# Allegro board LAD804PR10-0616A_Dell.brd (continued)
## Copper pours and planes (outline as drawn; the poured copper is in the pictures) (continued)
LX1_APU on BOTTOM (solid shape): 153.44,71.33 156.04,71.33 156.23,71.14 156.23,68.15 156.1,68.03 154.64,68.03 154.26,67.65 154.26,65.17 154.01,64.92 146.71,64.92 145.94,65.68 145.94,69.68 146.83,69.68 146.83,70.57 145.94,70.57 145.94,71.96 146.13,72.15 152.61,72.15
LX1_APU on IN2 (solid shape): 154.58,70.88 154.58,69.8 154.52,69.74 153.56,69.74 153.44,69.87 153.44,70.82 153.56,70.95 154.52,70.95
LX1_APU on IN2 (solid shape): 161.37,62.95 161.37,61.23 161.32,61.23 161.26,61.17 160.8,61.17 160.61,61.36 160.61,62.95 160.74,63.07 161.25,63.07
LX1_VGA on TOP (solid shape): 57.3,122.32 57.61,122.01 58.63,122.01 58.76,121.88 58.76,121.37 58.63,121.25 57.65,121.25 57.59,121.27 56.85,122.01 56.74,122.01 56.69,122.04 56.6,122.13 55.71,122.13 55.64,122.2 55.64,122.26 55.71,122.32 56.73,122.32
LX1_VGA on TOP (solid shape): 76.22,120.16 76.22,118.65 76.19,118.64 75.99,118.36 76.12,118.05 76.15,117.97 76.12,117.89 75.99,117.64 76.09,117.37 76.12,117.3 75.99,116.99 76.12,116.67 76.09,116.6 76,116.29 76.19,116.03 76.22,116.02 76.22,113.43 75.97,113.18 72.41,113.18 72.22,113.37 72.22,114.95 71.78,115.4 69.62,115.4 69.3,115.72 69.3,120.29 69.49,120.48 75.9,120.48
LX1_VGA on BOTTOM (solid shape): 75.84,120.16 75.84,115.4 75.97,115.27 77.68,115.27 78.06,114.89 78.06,111.02 78.95,111.02 78.95,112.1 79.01,112.16 80.35,112.16 80.54,111.97 80.54,109.75 80.28,109.49 75.65,109.49 75.39,109.75 75.39,110.89 75.2,111.08 72.98,111.08 72.66,111.4 72.66,115.4 72.47,115.59 69.55,115.59 69.3,115.84 69.3,120.29 69.49,120.48 75.52,120.48
LX1_VGA on IN2 (solid shape): 57.87,121.69 58.57,121.69 58.57,121.68 58.82,121.43 58.82,120.92 58.76,120.86 58.06,120.86 56.98,121.94 56.98,122.07 57.17,122.26 57.3,122.26
LX1_VGA on IN2 (solid shape): 74.67,118.85 74.7,118.79 74.7,118.48 74.69,118.47 74.66,118.32 74.69,118.17 74.7,118.16 74.7,117.85 74.67,117.79 74.63,117.75 74.12,117.75 73.93,117.56 73.55,117.56 73.49,117.62 73.49,118.83 73.55,118.89 74.63,118.89
LX2_VGA on TOP (solid shape): 59.07,124.8 59.07,124.29 59.01,124.23 57.3,124.23 57.17,124.1 55.77,124.1 55.71,124.17 55.71,124.29 55.77,124.36 56.79,124.36 56.85,124.42 57.17,124.42 57.49,124.74 57.8,124.74 57.93,124.86 59.01,124.86
LX2_VGA on TOP (solid shape): outline of 87 points within 69.3,121.43 77.43,131.97
LX2_VGA on BOTTOM (solid shape): 78.08,131.88 78.08,130.21 77.06,130.21 77.06,129.41 78.02,129.41 78.02,128.06 77.97,128.01 77.53,128.01 77.49,127.97 77.49,124.1 77.3,123.91 74.7,123.91 74.32,123.53 74.32,121.81 74.19,121.68 69.36,121.68 69.24,121.81 69.24,125.88 69.55,126.19 73.87,126.19 73.87,126.19 74.43,126.19 74.72,126.49 74.72,127.99 74.17,128.54 73.4,128.54 73.11,128.83 73.11,131.77 73.31,131.97 77.98,131.97
LX2_VGA on IN2 (solid shape): 59.58,125.5 59.58,125.44 58.44,124.29 57.42,124.29 57.36,124.36 57.36,124.61 58.57,125.82 59.26,125.82
LX2_VGA on IN2 (solid shape): 77.48,128.05 77.48,124.25 77.32,124.1 75.23,124.1 74.66,124.67 74.66,127.72 75.08,128.14 77.38,128.14
LX_1.2V on TOP (solid shape): 78.38,104.67 78.38,103.33 78.32,103.27 77.52,103.27 77.46,103.33 77.46,103.9 77.05,104.32 77.05,105.3 77.17,105.43 77.62,105.43
LX_1.2V on BOTTOM (solid shape): 77.68,106.76 77.68,103.59 78.19,103.08 81.05,103.08 81.11,103.02 81.11,102.06 80.98,101.94 74.63,101.94 74.19,102.38 74.19,106.83 74.32,106.95 77.49,106.95
LX_1.2V on BOTTOM (solid shape): 85.36,106.13 85.49,106.13 86.51,105.11 86.51,104.35 86.44,104.29 86.32,104.29 86.25,104.35 86.25,104.79 85.94,105.11 85.81,105.11 85.36,105.56 84.54,105.56 84.41,105.68 84.41,106.32 84.48,106.38 85.11,106.38
LX_1.2V on IN2 (solid shape): 77.87,105.3 77.87,103.21 77.74,103.08 77.11,103.08 76.98,103.21 76.98,105.3 77.11,105.43 77.74,105.43
LX_1.2V on IN2 (solid shape): 86.19,105.43 86.19,105.24 86.06,105.11 85.81,105.11 85.65,105.27 84.76,105.27 84.41,105.62 84.41,106 84.48,106.06 85.55,106.06
LX_1.8VALW on TOP (solid shape): 37.68,101.62 37.68,99.97 37.61,99.9 36.58,99.9 36.5,99.95 36.49,100.04 36.4,100.41 36.03,100.49 35.94,100.51 35.9,100.59 35.9,101.49 36.09,101.68 37.61,101.68
LX_1.8VALW on BOTTOM (solid shape): 38.66,103.99 38.66,103.37 38.76,103.27 39.52,103.27 39.71,103.08 39.71,99.84 36.56,99.84 36.47,99.89 36.47,99.99 36.42,100.39 36.03,100.49 35.94,100.51 35.9,100.59 35.9,101.63 35.94,101.71 36.03,101.73 36.37,101.78 36.51,102.08 36.53,102.16 36.61,102.19 37.68,102.19 37.8,102.32 37.8,103.97 37.9,104.07 38.58,104.07
LX_3V on TOP (solid shape): 172.36,49.68 172.36,49.17 172.49,49.04 172.93,49.04 172.99,48.98 172.99,48.15 172.8,47.96 172.3,47.96 171.22,49.04 169.88,49.04 169.69,49.23 169.69,50.18 169.88,50.37 171.66,50.37
LX_3V on BOTTOM (solid shape): 177.69,48.79 177.69,48.21 177.44,47.96 176.61,47.96 176.55,48.02 176.55,48.35 176.56,48.4 176.56,48.43 176.56,48.86 176.68,48.98 177.5,48.98
LX_3V on BOTTOM (solid shape): 172.61,50.23 172.61,49.76 172.58,49.74 172.54,49.13 173.09,49.39 173.13,49.46 173.2,49.48 173.69,49.48 174.25,48.92 174.25,48.43 174.26,48.4 174.26,48.36 174.26,47.58 174.2,47.52 173.45,47.52 173.45,47.52 173.03,47.52 173.02,47.55 172.55,47.79 172.35,47.3 172.37,47.27 172.3,47.2 172.3,45.23 172.17,45.1 171.63,45.1 171.54,45.19 171.34,45.19 171.21,45.17 171.1,45.1 169.76,45.1 169.63,45.23 169.63,49.9 170.03,50.31 172.54,50.31
LX_3V on IN2 (solid shape): 177.69,48.85 177.69,48.21 177.44,47.96 172.55,47.96 172.36,48.15 172.36,48.91 172.49,49.04 177.5,49.04
LX_5V on TOP (solid shape): 189.55,42.69 189.55,41.7 189.4,41.55 187.7,41.55 187.69,41.55 187.56,41.58 187.43,41.57 187.4,41.56 187.28,41.67 187.28,42.75 187.41,42.88 189.36,42.88
LX_5V on BOTTOM (solid shape): 199.6,38.88 199.6,38.05 199.41,37.86 198.14,37.86 198.08,37.93 198.08,38.12 198.33,38.37 198.33,38.69 198.65,39.01 199.47,39.01
LX_5V on BOTTOM (solid shape): outline of 169 points within 187.15,37.48 195.85,42.75
LX_5V on IN2 (solid shape): 196.24,38.94 199.54,38.94 199.6,38.88 199.6,37.99 199.47,37.86 196.11,37.86 195.66,37.42 194.46,37.42 194.2,37.67 194.2,38.84 194.74,38.84 194.74,38.79 194.74,38.74 194.76,38.69 194.78,38.64 194.81,38.59 194.85,38.56 194.89,38.52 194.94,38.5 194.99,38.48 195.04,38.46 195.09,38.46 195.15,38.46 195.2,38.48 195.25,38.5 195.29,38.52 195.33,38.56 195.37,38.59 195.4,38.64 195.42,38.69 195.44,38.74 195.45,38.79 195.45,38.84 195.44,38.9 195.42,38.95 195.4,38.99 195.37,39.04 195.33,39.08 195.29,39.11 195.25,39.14 195.2,39.16 195.15,39.17 195.09,39.17 195.04,39.17 194.99,39.16 194.94,39.14 194.89,39.11 194.85,39.08 194.81,39.04 194.78,38.99 194.76,38.95 194.74,38.9 194.74,38.84 194.2,38.84 194.2,39.13 194.46,39.39 195.79,39.39
LX_+1.35VGPU on BOTTOM (solid shape): 158.64,89.55 158.64,89.17 158.2,88.73 157.37,88.73 157.31,88.79 157.31,89.12 157.31,89.12 157.31,89.55 157.44,89.68 158.52,89.68
LX_+1.35VGPU on BOTTOM (solid shape): 152.55,92.98 152.55,92.09 152.8,91.84 154.07,91.84 154.13,91.78 154.13,90.32 154.9,89.55 154.9,89.05 155.02,88.92 155.02,88.41 154.9,88.28 153.12,88.28 152.99,88.16 152.99,86.95 152.55,86.51 150.71,86.51 150.52,86.7 150.52,92.92 150.71,93.11 152.42,93.11
LX_+1.35VGPU on IN2 (solid shape): 158.58,89.62 158.58,89.11 158.2,88.73 153.56,88.73 153.37,88.92 153.37,89.55 153.56,89.74 158.45,89.74
LX_NB on TOP (solid shape): 165.63,58.37 165.63,57.23 165.88,56.98 165.88,55.9 165.76,55.77 165.76,55.45 165.56,55.26 164.87,55.26 164.74,55.39 164.74,55.83 164.8,55.9 165.11,55.9 165.25,55.9 165.37,56.03 165.37,58.37 165.44,58.44 165.56,58.44
LX_NB on TOP (solid shape): 155.15,53.87 158.64,53.87 158.96,53.55 158.96,47.64 158.83,47.52 154.13,47.52 153.94,47.71 153.94,48.41 153.82,48.53 153.66,48.53 153.61,48.54 153.44,48.72 153.44,48.98 153.06,49.36 151.34,49.36 151.21,49.48 151.21,54.88 151.4,55.07 153.94,55.07
LX_NB on BOTTOM (solid shape): outline of 133 points within 150.13,47.45 158.83,56.53
LX_NB on IN2 (solid shape): 155.25,54.85 155.25,53.93 155.18,53.87 153.4,53.87 153.28,53.99 153.28,54.91 153.37,55.01 155.09,55.01
LX_NB on IN2 (solid shape): 165.88,57.04 165.88,55.41 165.88,55.39 165.88,55.14 165.69,54.95 165.25,54.95 165.12,55.07 165.12,55.64 165.37,55.9 165.37,57.04 165.44,57.1 165.82,57.1
LX_VDDP_ALWP on TOP (solid shape): 160.1,36.4 160.1,34.94 159.6,34.44 159.6,33.29 159.53,33.23 159.41,33.23 159.34,33.29 159.34,36.4 159.41,36.47 160.04,36.47
LX_VDDP_ALWP on TOP (solid shape): 151.34,40.53 151.34,37.61 151.15,37.42 149.88,37.42 149.56,37.1 149.56,35.83 148.67,34.94 148.67,30.88 148.55,30.75 145.37,30.75 145.12,30.5 144.52,30.5 144.14,30.88 144.14,38.42 146.44,40.72 151.15,40.72
LX_VDDP_ALWP on BOTTOM (solid shape): 150.89,40.15 150.89,38.91 153.5,36.3 153.5,34.63 153.25,34.37 151.48,34.37 151.47,34.4 151.43,34.46 151.38,34.52 151.34,34.59 151.38,34.67 151.5,35.02 151.25,35.28 151.18,35.36 151.21,35.45 151.21,35.95 150.71,35.96 150.64,35.93 150.57,35.96 149.97,35.71 150.57,35.45 150.64,35.48 150.71,35.45 150.78,35.4 150.86,35.36 150.93,35.29 150.9,35.2 150.79,34.93 150.92,34.67 150.96,34.59 150.92,34.52 150.87,34.46 150.83,34.4 150.82,34.37 150.13,34.37 149.05,35.45 146.07,35.45 145.69,35.83 145.69,40.4 145.89,40.61 150.43,40.61
LX_VDDP_ALWP on IN2 (solid shape): 150.01,37.74 150.01,36.47 149.94,36.4 149.18,36.4 148.99,36.59 148.99,37.61 149.18,37.8 149.94,37.8
LX_VDDP_ALWP on IN2 (solid shape): 160.23,36.21 160.23,34.75 160.04,34.56 159.53,34.56 159.41,34.69 159.41,35.45 158.83,36.02 158.83,36.09 159.21,36.47 159.98,36.47
MCT0 on TOP (solid shape): 19.26,112.54 19.26,111.52 19.2,111.46 17.61,111.46 17.55,111.52 17.55,112.67 17.61,112.73 19.07,112.73
MCT0 on BOTTOM (solid shape): 17.99,112.54 19.83,112.54 20.09,112.29 20.09,111.52 20.02,111.46 17.55,111.46 17.52,111.51 17.48,111.56 17.48,112.48 17.61,112.6 17.93,112.6
MCT1 on TOP (solid shape): 19.26,109.05 19.26,108.03 19.13,107.9 17.67,107.9 17.61,107.97 17.61,109.05 17.67,109.11 19.2,109.11
MCT1 on BOTTOM (solid shape): 18.5,108.79 19.96,108.79 20.21,108.54 20.21,108.03 20.09,107.9 17.74,107.9 17.55,108.1 17.55,108.92 17.74,109.11 18.18,109.11
Net_18 on TOP (solid shape): 152.04,83.37 144.04,83.37 144.04,91.37 152.04,91.37
Net_19 on TOP (solid shape): 208.13,15.89 200.13,15.89 200.13,23.89 208.13,23.89
PHASE_CHG on TOP (solid shape): 210.33,32.02 210.33,30.82 210.52,30.63 211.48,30.63 211.79,30.31 211.79,27.39 211.67,27.26 209.38,27.26 209,27.64 207.47,27.64 207.41,27.7 207.41,31.7 207.79,32.09 210.27,32.09
PHASE_CHG on TOP (solid shape): 209.75,42.11 209.9,42.08 210.05,42.11 210.06,42.12 210.14,42.12 210.23,42.03 210.42,42.03 210.46,41.99 211.91,41.99 211.91,41.8 211.84,41.74 210.4,41.74 210.24,41.58 209.22,41.58 209,41.36 209,40.79 208.87,40.66 208.33,40.66 208.25,40.73 208.25,41.32 208.34,41.32 208.91,41.88 208.91,41.94 209.05,42.08 209.12,42.08 209.14,42.07 209.42,42.07 209.43,42.08 209.44,42.08 209.48,42.12 209.74,42.12
PHASE_CHG on BOTTOM (solid shape): outline of 121 points within 207.03,27.58 214.08,32.85
PHASE_CHG on IN2 (solid shape): 209.32,29.86 209.32,28.97 209.19,28.85 208.24,28.85 208.11,28.97 208.11,29.99 208.24,30.12 209.06,30.12
PHASE_CHG on IN2 (solid shape): 209.75,42.11 209.9,42.08 210.05,42.11 210.06,42.12 210.33,42.12 210.4,42.06 210.4,41.17 210.14,40.91 209.25,40.91 209.06,41.1 209.06,41.93 209.21,42.07 209.23,42.07 209.35,42.07 209.46,42.12 209.74,42.12
RING2 on TOP (solid shape): 24.34,27.84 24.91,27.84 24.97,27.85 25.03,27.86 25.06,27.87 25.1,27.83 25.1,27.77 25.04,27.7 23,27.7 22.94,27.76 22.94,28.24 23.04,28.34 23.84,28.34
RING2 on BOTTOM (solid shape): 22.94,15.58 22.94,14.81 22.82,14.69 21.23,14.69 21.17,14.75 21.17,15.51 21.61,15.96 22.56,15.96
RING2 on IN2 (solid shape): 22.75,16.78 22.75,15.64 22.56,15.45 21.77,15.45 21.42,15.8 21.42,16.72 21.67,16.97 22.56,16.97
RING2 on IN2 (solid shape): 24.02,28.47 24.02,27.89 23.9,27.77 22.44,27.77 22.37,27.7 21.61,27.7 21.55,27.77 21.55,28.47 21.67,28.59 23.9,28.59
RING2_R on BOTTOM (solid shape): 17.48,13.77 17.48,13.04 17.23,12.78 15.7,12.78 15.26,13.23 15.26,14.24 15.39,14.37 16.89,14.37
RING2_R on BOTTOM (solid shape): 20.91,14.69 20.91,14.64 21.12,14.43 22.05,14.43 22.05,13.99 21.93,13.86 19.96,13.86 19.58,14.24 19.58,15.32 19.64,15.39 20.21,15.39
RING2_R on BOTTOM (solid shape): 4.72,13.8 4.72,12.21 4.53,12.02 3.13,12.02 3.07,12.08 3.07,12.09 2.78,12.38 2.78,13.75 3.02,13.99 4.53,13.99
RING2_R on IN1 (solid shape): 20.28,15.32 20.28,14.37 20.02,14.12 16.85,14.12 15.9,13.16 15.39,13.16 15.07,13.48 15.07,14.31 16.21,15.45 20.15,15.45
SLEEVE on TOP (solid shape): 24.4,27.51 25.31,27.51 25.37,27.45 25.37,27.31 25.32,27.26 24.34,27.26 24.21,27.13 23.96,27.13 23.93,27.11 23.93,27.11 23.7,26.88 23.13,26.88 22.95,27.06 22.95,27.46 23.07,27.58 24.34,27.58
SLEEVE on BOTTOM (solid shape): 23.01,18.62 23.01,17.5 22.92,17.42 21.23,17.42 21.17,17.48 21.17,18.56 21.36,18.75 22.88,18.75
SLEEVE on IN2 (solid shape): 23.01,19.7 23.01,18.24 22.82,18.05 21.86,18.05 21.74,18.18 21.74,19.77 21.8,19.83 22.88,19.83
SLEEVE on IN2 (solid shape): 24.66,27.32 24.66,26.5 24.59,26.43 23.07,26.43 22.85,26.66 22.85,27.29 23.07,27.51 24,27.51 24.07,27.58 24.4,27.58
SLEEVE_R on BOTTOM (solid shape): 21.1,17.16 21.12,17.16 21.99,17.16 22.05,17.1 22.05,16.4 21.99,16.34 20.78,16.34 20.53,16.08 19.32,16.08 19.2,16.21 19.2,17.1 19.32,17.23 21.04,17.23
SLEEVE_R on BOTTOM (solid shape): 4.15,25.1 4.15,22.88 3.89,22.62 2.18,22.62 1.99,22.81 1.99,24.74 2.48,24.96 2.9,25.29 3.96,25.29
SNUB_+1.35VGPU on BOTTOM (solid shape): 149.82,92.98 149.82,91.27 149.75,91.2 147.66,91.2 147.59,91.27 147.59,92.28 147.66,92.35 148.42,92.35 148.48,92.41 148.48,92.98 148.55,93.05 149.75,93.05
SPK_L+_CONN on TOP (solid shape): 43.77,6.3 43.77,5.03 42.76,5.03 42.69,5.1 42.69,6.18 42.88,6.37 43.71,6.37
SPK_L+_CONN on TOP (solid shape): 38.37,27.7 38.37,27.07 38.18,26.88 36.52,26.88 36.3,27.1 36.3,27.74 36.45,27.89 38.18,27.89
SPK_L+_CONN on TOP (solid shape): 10.82,11 10.82,9.86 10.75,9.8 10.31,9.8 10.24,9.86 10.24,10.24 10.12,10.37 9.48,10.37 9.42,10.43 9.42,10.94 9.55,11.07 10.75,11.07
SPK_L+_CONN on BOTTOM (solid shape): 10.75,11 10.75,9.86 10.12,9.23 10.12,4.91 10.05,4.84 9.61,4.84 9.48,4.97 9.48,6.88 9.29,7.07 9.29,8.1 9.29,8.12 9.29,8.63 9.29,8.65 9.29,9.67 9.1,9.86 9.1,10.94 9.35,11.19 10.56,11.19
SPK_L+_CONN on IN2 (solid shape): 43.84,5.73 43.84,4.91 43.77,4.84 42.12,4.84 41.99,4.97 41.99,5.8 42.06,5.86 43.71,5.86
SPK_L+_CONN on IN2 (solid shape): 11.07,10.94 11.07,9.16 11.2,9.04 11.2,8.46 10.5,8.46 10.12,8.84 10.12,11 10.18,11.07 10.94,11.07
SPK_L-_CONN on TOP (solid shape): 45.36,4.91 45.36,3.83 45.23,3.7 44.15,3.7 44.03,3.83 44.03,4.78 44.22,4.97 45.3,4.97
SPK_L-_CONN on TOP (solid shape): 38.44,29.04 38.44,28.28 38.37,28.21 36.45,28.21 36.3,28.36 36.3,29 36.46,29.16 38.31,29.16
SPK_L-_CONN on TOP (solid shape): 8.97,11 8.97,9.99 8.85,9.86 8.4,9.86 8.11,10.15 8.11,10.17 8.1,10.17 8.08,10.18 7.39,10.18 7.32,10.24 7.32,10.94 7.45,11.07 8.91,11.07
SPK_L-_CONN on BOTTOM (solid shape): 8.85,11.07 8.85,9.99 7.89,9.04 7.89,7.38 8.59,6.69 8.91,6.69 9.16,6.43 9.16,4.97 9.04,4.84 8.53,4.84 8.4,4.97 8.4,5.67 7.07,7 7.07,11 7.26,11.19 8.72,11.19
SPK_L-_CONN on IN2 (solid shape): 9.1,11 9.1,9.23 9.04,9.16 8.28,9.16 8.15,9.29 8.15,11.07 8.21,11.13 8.97,11.13
SPK_L-_CONN on IN2 (solid shape): 45.42,4.34 45.42,3.57 45.3,3.45 43.58,3.45 43.33,3.7 43.33,4.34 43.45,4.46 45.3,4.46
SPK_R+_CONN on TOP (solid shape): 14.88,11.07 14.88,10.11 14.75,9.99 14.43,9.99 14.12,10.31 13.42,10.31 13.36,10.37 13.36,11.07 13.42,11.13 14.82,11.13
SPK_R+_CONN on TOP (solid shape): 47.96,8.46 47.96,7.51 47.84,7.38 46.76,7.38 46.69,7.45 46.69,8.08 46.57,8.21 46.57,8.59 46.63,8.65 47.77,8.65
SPK_R+_CONN on TOP (solid shape): 38.5,31.64 38.5,30.82 38.44,30.75 37.99,30.75 37.84,30.74 37.69,30.69 36.49,30.69 36.29,30.89 36.29,31.55 36.52,31.77 38.37,31.77
SPK_R+_CONN on BOTTOM (solid shape): 14.88,11.13 14.88,10.11 14.31,9.54 14.31,7.96 12.21,5.86 12.21,4.97 12.15,4.91 11.64,4.91 11.51,5.03 11.51,6.39 11.54,6.4 11.6,6.44 11.66,6.48 12.56,7.38 12.78,7.38 12.92,7.52 12.93,7.52 13.17,7.67 13.32,7.91 13.32,7.93 13.42,8.02 13.42,9.48 13.16,9.73 13.16,11 13.36,11.19 14.82,11.19
SPK_R+_CONN on IN1 (solid shape): 15.9,11.04 15.9,10.08 15.77,9.96 14.56,9.96 14.37,10.15 14.37,11.04 14.5,11.16 15.77,11.16
SPK_R+_CONN on IN1 (solid shape): 47.96,8.15 47.96,7.51 47.71,7.26 46.12,7.26 46.06,7.32 46.06,8.21 46.12,8.27 47.84,8.27
SPK_R-_CONN on TOP (solid shape): 46.38,7.64 46.38,7.07 46.57,6.88 46.57,6.5 46.44,6.37 45.36,6.37 45.3,6.43 45.3,7.45 45.55,7.7 46.31,7.7
SPK_R-_CONN on TOP (solid shape): 12.91,11.07 12.91,9.86 12.85,9.8 12.47,9.8 12.34,9.92 12.34,10.11 12.21,10.24 11.39,10.24 11.32,10.31 11.32,11 11.45,11.13 12.85,11.13
SPK_R-_CONN on TOP (solid shape): 38.37,30.37 38.37,29.55 38.31,29.48 37.99,29.48 37.84,29.47 37.69,29.42 36.49,29.42 36.29,29.62 36.29,30.26 36.46,30.43 38.31,30.43
SPK_R-_CONN on BOTTOM (solid shape): 12.91,11.07 12.91,9.92 12.02,9.04 12.02,8.59 11.13,7.7 11.13,7.03 11.12,7.02 11.01,6.74 11.13,6.46 11.13,5.03 10.94,4.84 10.56,4.84 10.43,4.97 10.43,8.65 11.2,9.42 11.2,11 11.39,11.19 12.78,11.19
SPK_R-_CONN on IN1 (solid shape): 13.64,11.07 13.64,9.99 14.18,9.45 14.18,8.84 13.86,8.53 13.16,8.53 12.31,9.38 12.31,11.13 12.37,11.19 13.51,11.19
SPK_R-_CONN on IN1 (solid shape): 46.57,6.88 46.57,6.11 46.44,5.99 44.43,5.99 44.38,6.03 44.38,6.76 44.56,6.94 46.5,6.94
T-GND_L on TOP (solid shape): 22.12,119.08 22.12,117.43 21.23,116.54 21.23,108.16 21.04,107.97 19.96,107.97 19.9,108.03 19.9,119.02 20.15,119.27 21.93,119.27
T-GND_L on BOTTOM (solid shape): 23.45,119.27 23.45,117.56 23.26,117.37 21.29,117.37 21.1,117.56 21.1,119.27 21.23,119.4 23.32,119.4
TPAN_VDD_F on TOP (solid shape): 229.95,33.93 229.95,28.15 229.89,28.09 226.91,28.09 226.72,28.28 226.72,30.43 227.54,31.26 227.54,33.93 227.67,34.05 229.83,34.05
UG1_APU on TOP (solid shape): 163.15,61.93 163.35,61.93 164.49,61.93 164.55,61.87 164.55,61.74 164.49,61.68 163.02,61.68 162.96,61.61 162.01,61.61 161.95,61.68 161.95,62.06 162.01,62.12 162.96,62.12
UG1_APU on BOTTOM (solid shape): 156.23,72.66 156.23,72.03 156.17,71.96 153.82,71.96 153.75,72.03 153.75,72.66 153.82,72.73 156.17,72.73
UG1_APU on IN2 (solid shape): 155.98,72.41 155.98,71.84 155.86,71.73 154.88,71.73 154.86,71.71 153.88,71.71 153.72,71.87 153.72,72.44 153.88,72.6 155.79,72.6
UG1_APU on IN2 (solid shape): 162.98,63.12 163,63.02 162.93,62.95 162.66,62.57 162.99,62.25 163.06,62.22 163.09,62.15 163.09,61.8 162.96,61.68 162.01,61.68 161.95,61.74 161.95,63.07 162.01,63.14 162.96,63.14
UG1_VGA on TOP (solid shape): 56.67,121.88 56.79,121.88 57.68,120.99 57.68,120.74 57.61,120.67 57.3,120.67 56.79,121.18 56.79,121.33 56.79,121.34 56.81,121.44 56.79,121.53 56.79,121.56 56.66,121.69 55.77,121.69 55.71,121.75 55.71,121.88 55.77,121.94 56.61,121.94
UG1_VGA on BOTTOM (solid shape): 74.63,110.76 74.63,109.94 74.44,109.75 72.73,109.75 72.6,109.87 72.6,110.7 72.79,110.89 74.51,110.89
UG1_VGA on IN2 (solid shape): 74.73,111.49 74.73,109.97 74.54,109.78 73.52,109.78 73.39,109.9 73.39,111.56 73.55,111.71 74.51,111.71
UG1_VGA on IN2 (solid shape): 58.12,120.61 58.44,120.61 58.63,120.42 58.63,119.91 58.57,119.85 58.07,119.85 58.06,119.88 57.88,120.04 57.63,120.06 57.61,120.05 56.72,120.93 56.72,121.31 56.98,121.56 57.17,121.56
UG2_VGA on TOP (solid shape): 57.68,125.31 57.68,125.12 57.11,124.55 56.8,124.55 55.77,124.55 55.71,124.61 55.71,124.67 55.77,124.74 56.66,124.74 57.04,125.12 57.04,125.18 57.3,125.44 57.55,125.44
UG2_VGA on BOTTOM (solid shape): 74.56,127.93 74.56,126.76 74.37,126.57 73.27,126.57 73.1,126.75 73.1,127.94 73.29,128.14 74.35,128.14
UG2_VGA on IN2 (solid shape): 74.3,127.15 74.3,126.57 74.24,126.51 72.4,126.51 72.33,126.57 72.33,127.27 72.4,127.34 74.11,127.34
UG2_VGA on IN2 (solid shape): 58.88,126.52 58.88,126.39 57.23,124.74 57.23,124.67 57.11,124.55 56.91,124.55 56.79,124.67 56.79,125.63 57.8,126.64 58.76,126.64
UG_1.2V on BOTTOM (solid shape): 79.08,105.64 79.08,104.16 78.95,104.03 78.45,104.03 78.38,104.03 78.32,104.09 78.32,105.62 78.44,105.75 78.97,105.75
UG_1.2V on BOTTOM (solid shape): 86.89,105.75 86.89,104.3 86.84,104.25 86.73,104.25 86.67,104.31 86.67,105.14 86,105.81 86,106 86.19,106.19 86.44,106.19
UG_1.2V on IN2 (solid shape): 79.78,105.75 79.78,104.79 79.59,104.6 78.57,104.6 78.44,104.73 78.44,105.81 78.51,105.87 79.65,105.87
UG_1.2V on IN2 (solid shape): 86.95,106 86.95,105.43 86.76,105.24 86.63,105.24 85.43,106.44 85.43,106.51 85.68,106.76 86.19,106.76
UG_NB on TOP (solid shape): 165.25,58.37 165.24,58.32 165.24,57.51 165.25,57.48 165.25,56.22 165.06,56.03 164.8,56.03 164.74,56.09 164.74,57.1 164.93,57.3 164.93,57.37 164.93,58.37 164.99,58.44 165.18,58.44
UG_NB on BOTTOM (solid shape): 155.28,58.06 155.28,57.17 155.09,56.98 153.94,56.98 153.82,57.1 153.82,58.12 153.88,58.18 155.15,58.18
UG_NB on IN2 (solid shape): 155.91,58.12 155.91,57.3 155.85,57.23 153.88,57.23 153.82,57.3 153.82,58.12 153.88,58.18 155.85,58.18
UG_NB on IN2 (solid shape): 165.18,57.3 165.18,56.09 165.12,56.03 164.49,56.03 163.98,56.53 163.98,57.36 164.04,57.42 165.06,57.42
UG_VDDP_ALWP on TOP (solid shape): 151.28,36.72 151.28,35.51 151.15,35.39 150.07,35.39 149.94,35.51 149.94,36.72 150.01,36.78 151.21,36.78
UG_VDDP_ALWP on TOP (solid shape): 159.21,35.13 159.21,34.24 159.09,34.12 159.09,33.29 159.02,33.23 158.9,33.23 158.83,33.29 158.83,34.05 158.71,34.18 158.71,35.13 158.9,35.32 159.02,35.32
UG_VDDP_ALWP on IN2 (solid shape): 151.98,36.21 151.98,35.58 151.85,35.45 150.2,35.45 150.07,35.58 150.07,36.21 150.2,36.34 151.85,36.34
UG_VDDP_ALWP on IN2 (solid shape): 159.21,35.32 159.21,34.24 159.15,34.18 158.64,34.18 158.52,34.31 158.52,34.94 158.14,35.32 158.14,35.51 158.39,35.77 158.77,35.77
UGATE_CHG on TOP (solid shape): 211.94,41.52 211.94,41.36 211.87,41.28 211.84,41.3 211.8,41.31 211.75,41.32 211.05,41.32 211.03,41.31 210.9,41.24 210.83,41.1 210.82,41.09 210.77,41.06 210.72,41.03 210.47,40.78 209.38,40.78 209.31,40.85 209.31,41.44 209.32,41.45 210.02,41.45 210.09,41.44 210.16,41.45 210.29,41.45 210.32,41.48 210.33,41.48 210.46,41.61 211.86,41.61
VL on BOTTOM (solid shape): 196.17,35.96 196.17,35.26 195.79,34.88 195.79,33.87 195.79,33.8 195.72,33.73 195.7,33.74 195.57,33.73 195.45,33.67 194.84,33.67 194.77,33.74 194.77,34.56 195.92,35.71 195.92,35.96 195.98,36.02 196.11,36.02
N17382859 on BOTTOM (solid shape): 129.24,21.35 129.24,20.66 129.69,20.21 130.13,20.21 130.13,19.7 130.7,19.7 130.7,20.21 130.96,20.21 130.96,19.7 131.53,19.7 131.53,20.21 132.41,20.21 133.95,18.67 133.95,15.99 134.26,15.68 134.26,15 134.13,14.88 133.31,14.88 132.86,15.32 130.83,15.32 130,16.15 130,18.31 129.75,18.56 129.61,18.56 127.67,18.56 127.27,18.56 127.15,18.69 127.15,19.64 127.66,19.64 127.66,20.27 127.15,20.27 127.15,20.47 127.66,20.47 127.66,21.04 127.15,21.04 127.15,21.42 129.18,21.42
N17415515 on TOP (solid shape): 169.37,124.99 169.37,123.46 168.96,123.05 168.96,121.79 168.91,121.68 168.91,120.38 168.43,119.91 168.43,119.58 168.18,119.32 166.38,119.32 166.05,119.65 166.05,119.77 166.06,119.77 166.06,120.25 166.61,120.25 166.61,120.75 166.06,120.75 166.06,121.05 166.61,121.05 166.61,121.55 166.06,121.55 166.06,122.03 166.05,122.03 166.05,124.9 166.39,125.24 169.12,125.24
N17481633 on TOP (solid shape): 212.55,35.83 212.55,35.21 212.55,35.2 212.74,35.01 212.74,32.1 212.75,32.02 213.44,31.32 213.44,30.88 213.32,30.75 212.75,30.75 212.68,30.82 212.68,30.94 211.73,31.9 211.73,32.15 211.48,32.4 207.41,32.4 207.28,32.53 207.28,34.63 207.67,35.01 210.9,35.01 211.86,35.96 212.43,35.96
N17481633 on BOTTOM (solid shape): 208.36,38.5 210.65,38.5 211.22,37.93 211.47,37.93 211.47,37.93 212.43,37.93 212.49,37.86 212.49,36.21 212.68,36.02 212.68,33.17 213.44,32.4 213.44,31.7 213.38,31.64 211.98,31.64 211.03,32.59 211.03,33.1 210.9,33.23 207.47,33.23 207.35,33.36 207.35,36.02 207.86,36.02 207.86,36.85 207.35,36.85 207.35,37.23 207.86,37.23 207.86,38.05 207.35,38.05 207.35,38.69 207.47,38.82 208.05,38.82
N20135074 on TOP (solid shape): 70.89,114.95 70.89,113.24 70.82,113.18 69.74,113.18 69.36,113.56 68.73,113.56 68.66,113.62 68.66,114.51 68.73,114.57 69.36,114.57 69.81,115.02 70.82,115.02
N20135197 on TOP (solid shape): 71.2,128.92 71.2,127.21 71.14,127.15 69.93,127.15 69.87,127.21 69.87,127.46 69.81,127.53 69.04,127.53 68.98,127.59 68.98,128.86 69.11,128.99 71.14,128.99
N20135251 on TOP (solid shape): 53.61,127.59 53.61,125.31 53.55,125.25 52.66,125.25 52.6,125.31 52.6,127.65 52.74,127.79 53.41,127.79
N20141477 on TOP (solid shape): 153.06,49.04 153.06,47.33 152.74,47.01 151.47,47.01 151.21,47.26 151.21,49.04 151.28,49.1 152.99,49.1
N20141719 on TOP (solid shape): 148.99,66.5 148.99,65.42 148.61,65.04 148.61,64.34 148.55,64.28 147.66,64.28 147.59,64.34 147.59,65.11 147.15,65.55 147.15,66.57 147.21,66.63 148.86,66.63
N20277901 on BOTTOM (solid shape): 153.44,33.1 153.44,31.39 153.06,31.01 152.29,31.01 152.17,31.13 152.17,31.9 152.04,32.02 151.66,32.02 151.59,32.09 151.59,33.1 151.72,33.23 153.31,33.23
N21021316 on TOP (solid shape): 160.1,37.67 160.1,36.78 160.04,36.72 159.15,36.72 158.96,36.91 158.06,36.91 158.01,36.96 158.01,37.67 158.07,37.74 160.04,37.74
N21022260 on TOP (solid shape): 164.87,55.01 165.37,55.01 165.44,54.95 165.44,54.37 165.37,54.31 164.87,54.31 164.55,54.63 163.53,54.63 163.47,54.69 163.47,55.33 163.53,55.39 164.49,55.39
N21022300 on TOP (solid shape): 162.58,64.28 162.58,63.65 162.52,63.58 161.56,63.58 161.12,63.14 160.55,63.14 160.48,63.2 160.48,63.71 160.55,63.77 161.06,63.77 161.63,64.34 162.52,64.34
N22643429 on BOTTOM (solid shape): 36.09,116.86 36.79,116.86 37.23,116.41 37.23,115.91 37.17,115.84 36.66,115.84 35.71,116.79 35.07,116.79 35.01,116.86 35.01,116.92 35.07,116.99 35.96,116.99
N22657839 on TOP (solid shape): 26.31,32.91 26.31,32.34 27.01,31.64 27.01,30.71 27.07,30.65 27.07,29.84 27.02,29.79 26.91,29.79 26.85,29.85 26.85,30.75 26.88,30.78 26.88,31.07 26.85,31.1 26.86,31.12 26.75,31.38 26.48,31.49 26.46,31.49 26.12,31.83 25.75,31.83 25.37,32.21 23.96,32.21 23.83,32.34 23.83,32.9 23.86,32.93 24.44,32.93 24.49,32.97 26.25,32.97
N22661096 on TOP (solid shape): 26.69,24.54 26.69,23.39 26.06,22.75 26.05,22.74 26.05,21.35 25.93,21.23 24.34,21.23 24.21,21.35 24.21,22.12 24.82,22.72 25.64,22.72 26.44,23.51 26.44,24.52 26.51,24.59 26.63,24.59
N22662054 on TOP (solid shape): 28.47,32.66 28.47,32.32 28.21,32.07 28.19,32.07 27.82,31.81 27.9,31.35 27.9,29.85 27.84,29.79 27.7,29.79 27.64,29.85 27.64,30.88 27.51,31.01 27.51,32.36 27.46,32.41 27.46,32.63 27.57,32.73 28.39,32.73
N22663765 on TOP (solid shape): 27.07,24.53 27.07,23.2 27.01,23.13 27,22.91 27.01,22.86 27.01,22.43 27.11,22.33 27.11,21.23 26.31,21.23 26.18,21.35 26.18,22.69 26.82,23.32 26.82,24.55 26.87,24.6 27,24.6
N24135897 on TOP (solid shape): 123.85,8.08 123.85,7.45 124.33,6.96 124.34,6.95 124.72,6.56 125.27,6.61 125.28,6.62 125.31,6.62 125.81,7.13 130.26,7.13 131.08,6.3 132.04,6.3 132.42,5.92 132.42,5.39 132.15,5.12 130.74,5.12 129.43,6.43 126.19,6.43 125.99,6.23 123.1,6.23 122.38,6.94 122.38,7.96 122.7,8.27 123.65,8.27
N24135899 on TOP (solid shape): 119.46,11.07 119.46,8.34 119.22,8.09 119.22,6.9 119.88,6.24 120.99,6.24 121.56,5.67 121.56,4.78 121.31,4.53 120.67,4.53 120.54,4.65 120.54,4.84 119.5,5.89 119.39,6.03 119.26,6.13 119.25,6.14 118.7,6.69 118.7,9.1 117.88,9.92 117.88,10.94 118.19,11.26 119.27,11.26
N25997876 on BOTTOM (solid shape): 165.15,119.21 165.15,117.77 164.83,117.45 161.84,117.45 161.25,116.86 161.25,114.37 161.01,114.13 159.7,114.13 159.52,114.31 159.52,117.59 159.58,117.8 159.52,118 159.52,118.15 160.78,119.41 164.94,119.41
N25997876 on IN2 (solid shape): 165.15,119.21 165.15,117.77 164.83,117.45 161.84,117.45 161.25,116.86 161.25,114.37 161.01,114.13 159.72,114.13 159.6,114.25 159.6,118.24 160.78,119.41 164.94,119.41
N27700813 on BOTTOM (solid shape): outline of 97 points within 22.32,91.97 28.21,96.27
N27700813 on IN1: 13.71,87.37 14.31,87.37 14.64,87.04 14.64,86 14.63,85.98 14.63,82.11 15.16,81.58 15.16,79.15 14.92,78.91 14.22,78.91 14.04,79.09 14.04,81.21 13.47,81.78 13.47,87.13
N28714524 on TOP (solid shape): 212.94,40.72 212.94,37.55 212.81,37.42 211.73,37.42 211.67,37.48 211.67,38.3 211.69,38.33 211.74,38.38 212.33,38.38 212.38,38.44 212.62,38.44 212.75,38.56 212.75,40.72 212.81,40.79 212.87,40.79
N28714564 on TOP (solid shape): 207.92,39.55 207.73,39.36 206.97,39.36 206.9,39.42 206.9,40.37 207.28,40.75 207.28,41.32 207.92,41.32
N28714601 on TOP (solid shape): 213.38,40.66 213.38,39.55 213.38,39.54 213.34,39.39 213.38,39.24 213.38,39.22 213.37,39.12 213.38,39.02 213.38,39.01 213.39,39 213.47,38.87 213.6,38.79 213.82,38.56 213.82,37.55 213.76,37.48 213.13,37.48 213.06,37.55 213.06,39.77 213.13,39.83 213.13,40.66 213.19,40.72 213.32,40.72
N28714606 on TOP (solid shape): 211.48,31.96 211.48,31.01 211.41,30.94 210.59,30.94 210.52,31.01 210.52,31.96 210.59,32.02 211.41,32.02
N28714606 on TOP (solid shape): 210.35,39.97 210.35,39.16 210.04,38.85 209.77,38.85 209.67,38.75 208.87,38.75 208.81,38.82 208.81,39.2 208.87,39.26 209.19,39.26 209.32,39.39 209.32,40.05 209.37,40.1 210.22,40.1
N28714606 on IN2 (solid shape): 211.54,31.96 211.54,31.01 211.48,30.94 210.46,30.94 210.33,31.07 210.33,31.83 210.65,32.15 211.35,32.15
N28714606 on IN2 (solid shape): 210.08,39.13 210.08,38.73 210.21,38.61 210.21,38.18 210.08,38.05 209,38.05 208.81,38.25 208.81,39.13 209,39.32 209.89,39.32
N28714617 on BOTTOM (solid shape): 166.14,114.05 166.24,113.95 166.24,113.41 166.28,113.37 166.28,112.67 165.96,112.35 164.31,112.35 163.42,111.46 163.42,111.15 161.88,111.15 161.88,110.51 163.42,110.51 163.42,109.8 163.41,109.79 163.41,109.66 163.29,109.54 161.92,109.54 161.81,109.66 161.5,109.66 161.04,110.12 161.04,112.57 161.5,113.02 161.5,116.78 162.03,117.32 166.14,117.32
N28714693 on TOP (solid shape): 206.14,30.75 206.14,27.2 206.01,27.07 203.62,27.07 203.6,27.1 203.28,27.3 202.96,27.1 202.95,27.07 202.59,27.07 202.39,27.26 202.39,30.69 202.59,30.88 206.01,30.88
N28714693 on BOTTOM (solid shape): outline of 82 points within 203.47,24.28 216.11,29.04
N28714782 on BOTTOM (solid shape): 217,32.59 217,29.36 216.87,29.23 215.6,29.23 215.54,29.29 215.54,31.01 216.05,31.51 216.05,32.53 216.24,32.72 216.87,32.72
N28714793 on TOP (solid shape): 207.03,30.75 207.03,28.28 207.28,28.02 207.28,27.65 207.28,27.65 207.28,27.32 207.22,27.26 206.33,27.26 206.27,27.32 206.27,30.82 206.33,30.88 206.9,30.88
N33124395 on BOTTOM (solid shape): 84.48,102.89 85.99,102.89 86.07,102.81 86.07,102.68 86.03,102.63 84.42,102.63 84.28,102.63 84.16,102.51 84.16,102.37 84.16,101.17 84.09,101.11 83.46,101.11 83.4,101.17 83.4,101.34 83.4,101.35 83.46,101.56 83.4,101.77 83.4,102.11 83.46,102.32 83.4,102.53 83.4,103.21 83.46,103.27 84.09,103.27
N33124472 on TOP (solid shape): 77.3,103.87 77.3,103.33 76.86,102.89 76.86,101.3 76.73,101.17 75.84,101.17 75.78,101.24 75.78,103.71 76,103.94 77.24,103.94
N39282118 on BOTTOM (solid shape): 39.33,108.6 39.9,108.6 39.9,109.11 40.98,109.11 41.04,109.05 41.04,106.32 40.91,106.19 37.93,106.19 37.87,106.25 37.87,108.98 37.99,109.11 38.5,109.11 38.5,108.6 39.07,108.6 39.07,109.17 39.33,109.17
N39282176 on TOP (solid shape): 40.91,102.51 40.91,99.97 40.85,99.9 39.2,99.9 39.14,99.97 39.14,102.38 39.33,102.57 40.85,102.57
N39352229 on BOTTOM (solid shape): 172.74,51.01 173.51,51.01 173.6,50.92 173.6,49.95 173.55,49.9 172.82,49.9 172.77,49.95 172.77,50.46 172.64,50.59 171.95,50.59 171.9,50.64 171.9,51.15 171.98,51.23 172.52,51.23
N39352417 on BOTTOM (solid shape): 195.92,36.72 195.92,36.21 194.52,34.82 194.52,33.74 194.46,33.67 194.29,33.67 194.28,33.68 194.07,33.74 193.86,33.67 193.57,33.67 193.5,33.74 193.5,36.09 194.27,36.85 195.79,36.85
N39352440 on BOTTOM (solid shape): 196.68,41.94 196.68,41.36 196.62,41.29 194.84,41.29 194.77,41.36 194.77,41.8 194.9,41.93 195.47,41.93 195.52,41.97 196.65,41.97

Small or netless copper shapes (teardrops, artwork), in the pictures only: 170 on TOP, 16 on BOTTOM, 1 on VCC, 1 on IN1, 1 on IN2, 1 on GND

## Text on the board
Ref Des/Silkscreen Bottom: SPK | 15"(M2.5X5L) | 17"(M2X3L) | RTC | (M2X3L) | 17" | H11 | H8 | CLEAR CMOS | H9 | H10 | KB | TP | BL | LED | IO | Fan | ODD | HDD | BATTERY | DIMM B | SUPPORT DDR4 | SODIMM-ONLY | DIMM A | SODIMM-ONLY SUPPORT DDR4 | EDP
User.Comments: LA-D804P | 2016-06-17 | 2017-06-17 | Moopi | BAL23 | 1.0(A00)
Ref Des/Silkscreen Top: UL indicator | VENDOR: | BAL23 LA-D804P | Made In Taiwan | Rev:1.0(A00) | 2016-06-17 | PWR | e1 | Pb | LA-D80 | DC | IN
User.14: LAYER | NAME | L3 | L1 | L2 | L5 | L4 | L6 | LA-D804P | GND | TOP | VCC | IN1 | IN2 | BOT | LS-XXXXP
User.45: FIGURE | SIZE | 8.0 | 22.0 | 28.0 | 35.0 | 118.0 | 126.0 | 138.0 | 146.0 | 154.0 | 236.0 | 43.0 | 63.0 | 220.0 | 55.0x24.0 | 63.0x24.0 | 63.0x35.0 | 71.0x31.0 | 79.0x31.0 | 126.0x102.0 | 169.0x146.0 | DRILL CHART: TOP to BOTTOM | ALL UNITS ARE IN MILS | TOLERANCE | +3.0/-3.0 | +2.0/-2.0 | PLATED | NON-PLATED | QTY | 4877 | 19 | 18 | 8 | 5 | 1 | 3 | 7 | 4
